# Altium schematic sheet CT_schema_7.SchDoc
size 274 x 160 mm
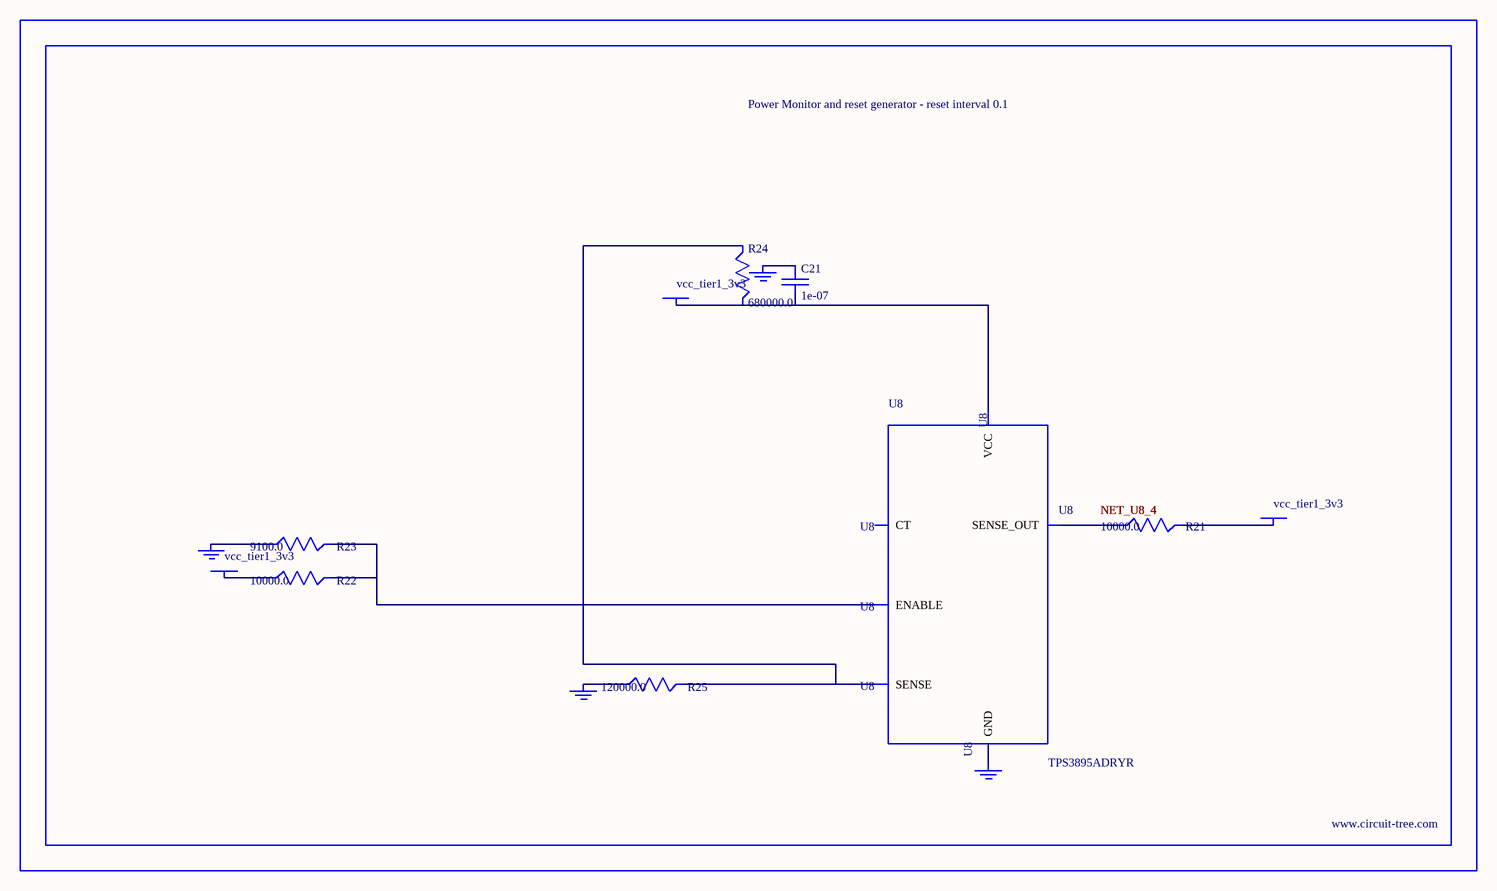
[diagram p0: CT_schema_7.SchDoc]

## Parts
BORDER6  (no value)
C21  1e-07  [C0402]
GND_INSTANCE_6_0  (no value)
GND_INSTANCE_6_1  (no value)
GND_INSTANCE_6_2  (no value)
GND_INSTANCE_6_3  (no value)
POWER_INSTANCE_6_0  vcc_tier1_3v3
POWER_INSTANCE_6_1  vcc_tier1_3v3
POWER_INSTANCE_6_2  vcc_tier1_3v3
R21  10000.0  [R0603]
R22  10000.0  [R0603]
R23  9100.0  [R0603]
R24  680000.0  [R0603]
R25  120000.0  [R0603]
U8  TPS3895ADRYR  [SON-6]

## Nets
NetC21_1: C21.1 GND_INSTANCE_6_2.0(GND)
NetC21_2: C21.2 POWER_INSTANCE_6_2.0(PWR) R24.2 U8.6(VCC)
NetGND_INSTANCE_6_0_0: GND_INSTANCE_6_0.0(GND) R23.1
NetGND_INSTANCE_6_1_0: GND_INSTANCE_6_1.0(GND) R25.1
NetGND_INSTANCE_6_3_0: GND_INSTANCE_6_3.0(GND) U8.2(GND)
NetPOWER_INSTANCE_6_0_0: POWER_INSTANCE_6_0.0(PWR) R22.1
NetPOWER_INSTANCE_6_1_0: POWER_INSTANCE_6_1.0(PWR) R21.2
NetR21_1: R21.1 U8.4(SENSE_OUT)
NetR22_2: R22.2 R23.2 U8.1(ENABLE)
NetR24_1: R24.1 R25.2 U8.3(SENSE)

Not connected (* = marked no-connect by the designer): U8 5(CT)

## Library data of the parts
BORDER6 = BORDER_PAGE6
C21 = C0402C104K3RACTU
GND_INSTANCE_6_0-GND_INSTANCE_6_3 = GND
POWER_INSTANCE_6_0-POWER_INSTANCE_6_2 = PWR
R21 R22 = RC0603JR-0710KL
R23 = RC0603JR-079K1L
R24 = RC0603JR-07680KL
R25 = RC0603JR-07120KL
